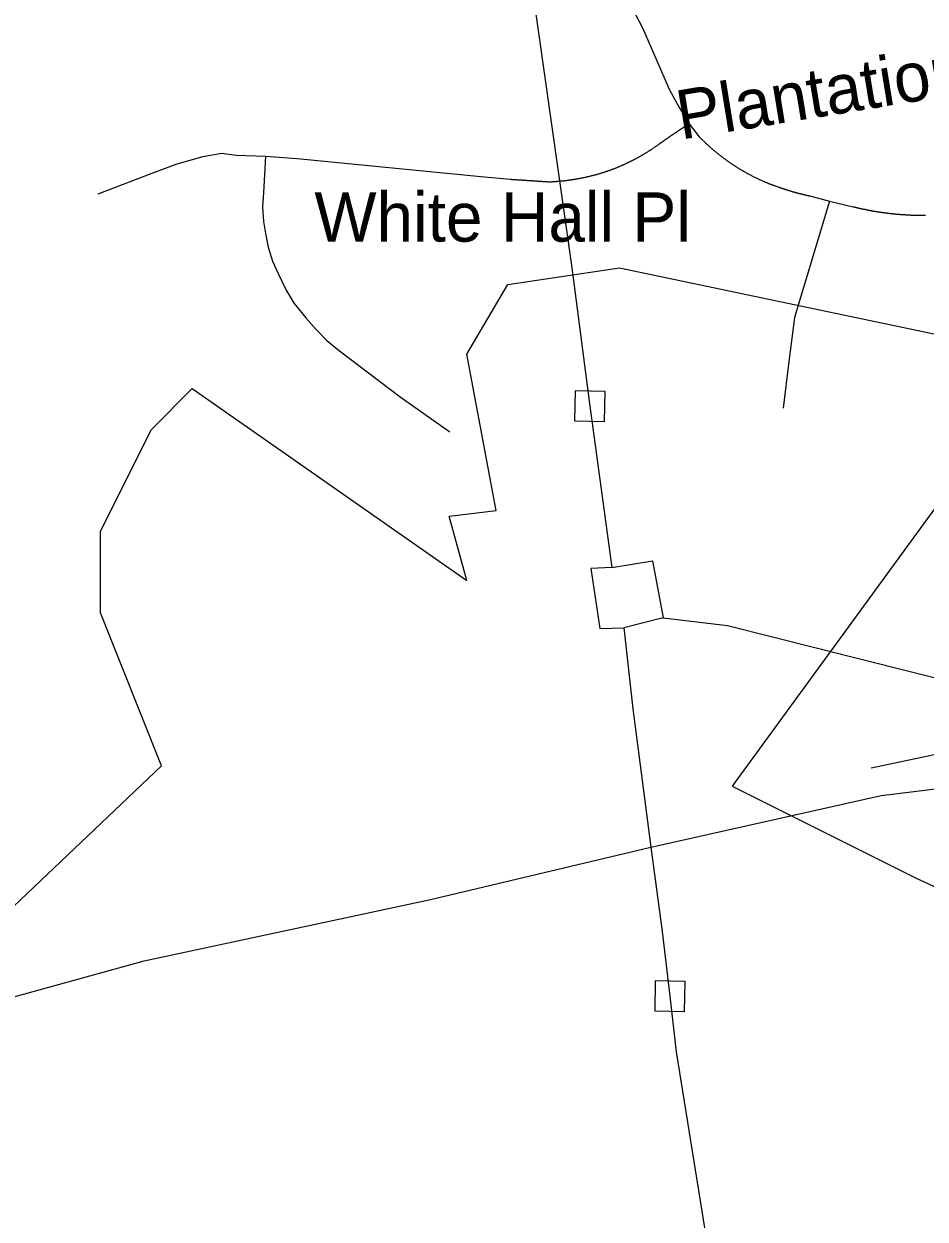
# Model space of a CAD drawing. Extents: x 1268485 to 1426702, y 514839 to 616766.
# Drawn here: x 1349734 to 1350936, y 537670 to 539264 of the extents above; entities that cross this region are included whole.
import ezdxf

# ---------------------------------------------------------------- set-up
doc = ezdxf.new("R2010")
doc.units = 0
for name, color, linetype in [('Old_Level_10', 7, 'Continuous'), ('Old_Level_35', 7, 'Continuous'), ('Old_Level_48', 7, 'Continuous'), ('Old_Level_49', 7, 'Continuous'), ('Old_Level_56', 7, 'Continuous')]:
    doc.layers.add(name, color=color, linetype=linetype)

msp = doc.modelspace()

# ---------------------------------------------------------------- linework, layer by layer
at = {"layer": 'Old_Level_35'}
for p, q in [((1350621.787, 539131.294), (1350635.218, 539113.762)), ((1350782.65, 539034.92), (1350808.897, 539027.794)), ((1350808.897, 539027.794), (1350840.372, 539020.617)), ((1351045.117, 538310.061), (1350864.261, 538271.613))]:
    msp.add_line(p, q, dxfattribs=at)
for points in [[(1350445.134, 539376.332), (1350463.384, 539365.464), (1350472.509, 539359.568), (1350482.249, 539350.751), (1350495.167, 539339.627), (1350509.11, 539327.58), (1350523.464, 539313.175), (1350536.485, 539297.437), (1350549.506, 539277.957), (1350559.656, 539258.939), (1350583.339, 539204.19), (1350594.925, 539177.328), (1350607.843, 539153.645), (1350621.787, 539131.294)], [(1350579.751, 539102.792), (1350580.264, 539103.15), (1350580.674, 539103.458), (1350580.981, 539103.663), (1350581.494, 539104.022), (1350581.904, 539104.33), (1350582.212, 539104.638), (1350582.724, 539104.893), (1350583.134, 539105.201), (1350583.544, 539105.509), (1350583.955, 539105.816), (1350584.365, 539106.073), (1350584.877, 539106.38), (1350585.287, 539106.688), (1350585.595, 539106.996), (1350586.108, 539107.252), (1350586.518, 539107.559), (1350586.825, 539107.867), (1350587.338, 539108.123), (1350587.748, 539108.431), (1350588.158, 539108.739), (1350588.671, 539109.046), (1350588.978, 539109.302), (1350589.388, 539109.61), (1350589.901, 539109.917), (1350590.209, 539110.174), (1350590.619, 539110.481), (1350591.131, 539110.789), (1350591.541, 539111.045), (1350591.849, 539111.353), (1350592.362, 539111.712), (1350592.772, 539111.917), (1350593.284, 539112.275), (1350593.592, 539112.583), (1350594.002, 539112.788), (1350594.515, 539113.147), (1350594.925, 539113.455), (1350595.232, 539113.711), (1350595.745, 539114.018), (1350596.155, 539114.326), (1350596.668, 539114.583), (1350596.975, 539114.89), (1350597.385, 539115.198), (1350597.898, 539115.454), (1350598.206, 539115.761), (1350598.616, 539116.018), (1350599.128, 539116.325), (1350599.538, 539116.633), (1350600.051, 539116.889), (1350600.359, 539117.197), (1350600.769, 539117.453), (1350601.281, 539117.761), (1350601.589, 539118.068), (1350602.102, 539118.324), (1350602.512, 539118.632), (1350602.922, 539118.889), (1350603.332, 539119.196), (1350603.742, 539119.504), (1350604.255, 539119.76), (1350604.665, 539120.067), (1350604.972, 539120.324), (1350605.485, 539120.632), (1350605.895, 539120.887), (1350606.408, 539121.195), (1350606.715, 539121.503), (1350607.125, 539121.759), (1350607.638, 539122.067), (1350608.048, 539122.323), (1350608.458, 539122.63), (1350608.868, 539122.887), (1350609.278, 539123.195), (1350609.791, 539123.451), (1350610.099, 539123.758), (1350610.611, 539124.015), (1350611.021, 539124.323), (1350611.329, 539124.578), (1350611.842, 539124.886), (1350612.252, 539125.143), (1350612.764, 539125.45), (1350613.174, 539125.706), (1350613.585, 539126.014), (1350613.995, 539126.271), (1350614.405, 539126.578), (1350614.917, 539126.834), (1350615.225, 539127.142), (1350615.738, 539127.398), (1350616.148, 539127.706), (1350616.66, 539127.962), (1350616.968, 539128.269), (1350617.378, 539128.526), (1350617.891, 539128.834), (1350618.301, 539129.039), (1350618.711, 539129.397), (1350619.121, 539129.602), (1350619.634, 539129.961), (1350620.044, 539130.166), (1350620.351, 539130.422), (1350620.864, 539130.73), (1350621.274, 539130.987), (1350621.787, 539131.294)], [(1350635.218, 539113.762), (1350636.038, 539112.993), (1350636.755, 539112.275), (1350637.473, 539111.507), (1350638.293, 539110.737), (1350639.011, 539110.02), (1350639.729, 539109.251), (1350640.549, 539108.482), (1350641.267, 539107.764), (1350641.984, 539106.996), (1350642.907, 539106.226), (1350643.625, 539105.509), (1350644.342, 539104.791), (1350645.163, 539104.073), (1350645.983, 539103.356), (1350646.7, 539102.638), (1350647.521, 539101.92), (1350648.238, 539101.202), (1350649.161, 539100.485), (1350649.879, 539099.767), (1350650.801, 539099.049), (1350651.519, 539098.383), (1350652.339, 539097.666), (1350653.16, 539096.999), (1350653.877, 539096.333), (1350654.8, 539095.615), (1350655.62, 539094.948), (1350656.338, 539094.231), (1350657.261, 539093.565), (1350657.978, 539092.898), (1350658.901, 539092.18), (1350659.721, 539091.514), (1350660.541, 539090.899), (1350661.362, 539090.181), (1350662.284, 539089.566), (1350663.002, 539088.899), (1350663.925, 539088.233), (1350664.745, 539087.567), (1350665.668, 539086.951), (1350666.385, 539086.336), (1350667.206, 539085.619), (1350668.128, 539085.003), (1350669.051, 539084.388), (1350669.871, 539083.773), (1350670.794, 539083.107), (1350671.614, 539082.492), (1350672.537, 539081.877), (1350673.357, 539081.262), (1350674.28, 539080.697), (1350675.1, 539080.082), (1350676.023, 539079.416), (1350676.843, 539078.801), (1350677.766, 539078.237), (1350678.586, 539077.621), (1350679.509, 539077.058), (1350680.329, 539076.443), (1350681.252, 539075.879), (1350682.174, 539075.315), (1350682.995, 539074.751), (1350684.02, 539074.136), (1350684.84, 539073.572), (1350685.763, 539073.008), (1350686.583, 539072.444), (1350687.608, 539071.88), (1350688.531, 539071.317), (1350689.351, 539070.752), (1350690.274, 539070.24), (1350691.299, 539069.676), (1350692.119, 539069.112), (1350693.042, 539068.651), (1350693.965, 539068.087), (1350694.888, 539067.574), (1350695.913, 539067.01), (1350696.733, 539066.498), (1350697.758, 539065.934), (1350698.579, 539065.421), (1350699.501, 539064.96), (1350700.527, 539064.447), (1350701.347, 539063.935), (1350702.372, 539063.422), (1350703.397, 539062.96), (1350704.218, 539062.448), (1350705.243, 539061.935), (1350706.166, 539061.422), (1350707.088, 539061.012), (1350708.114, 539060.5), (1350709.036, 539059.987), (1350709.959, 539059.577), (1350710.882, 539059.064), (1350711.907, 539058.603), (1350712.83, 539058.142), (1350713.855, 539057.681), (1350714.778, 539057.27), (1350715.7, 539056.809), (1350716.726, 539056.399), (1350717.751, 539055.886), (1350718.674, 539055.425), (1350719.596, 539055.066), (1350720.622, 539054.605), (1350721.647, 539054.195)], [(1349833.259, 539037.585), (1349907.59, 539066.293), (1349937.425, 539077.366), (1349973.002, 539087.311), (1349998.326, 539091.77), (1350017.293, 539089.259), (1350056.458, 539088.131)], [(1350056.458, 539088.131), (1350055.228, 539062.858), (1350053.792, 539039.482), (1350052.665, 539020.617), (1350053.792, 539000.624), (1350056.458, 538984.835), (1350060.251, 538966.688), (1350065.89, 538947.824), (1350073.375, 538931.624), (1350084.038, 538909.376), (1350094.905, 538891.332), (1350110.387, 538872.416), (1350123.51, 538857.396), (1350138.581, 538842.273), (1350155.293, 538828.33), (1350236.289, 538766.865), (1350302.623, 538720.523)], [(1350056.458, 539088.131), (1350099.006, 539084.747), (1350343.736, 539060.961), (1350383.414, 539057.168)], [(1350514.954, 539068.856), (1350515.672, 539069.112), (1350516.39, 539069.369), (1350517.005, 539069.624), (1350517.723, 539069.881), (1350518.338, 539070.189), (1350519.158, 539070.445), (1350519.876, 539070.701), (1350520.491, 539070.957), (1350521.209, 539071.265), (1350521.926, 539071.522), (1350522.644, 539071.727), (1350523.259, 539072.085), (1350523.977, 539072.29), (1350524.592, 539072.547), (1350525.412, 539072.854), (1350526.027, 539073.11), (1350526.745, 539073.418), (1350527.36, 539073.725), (1350528.078, 539073.982), (1350528.795, 539074.29), (1350529.513, 539074.546), (1350530.128, 539074.853), (1350530.743, 539075.213), (1350531.461, 539075.52), (1350532.076, 539075.776), (1350532.897, 539076.084), (1350533.512, 539076.391), (1350534.229, 539076.699), (1350534.845, 539077.006), (1350535.46, 539077.314), (1350536.28, 539077.621), (1350536.895, 539077.929), (1350537.613, 539078.237), (1350538.228, 539078.544), (1350538.843, 539078.852), (1350539.663, 539079.211), (1350540.278, 539079.519), (1350540.894, 539079.826), (1350541.611, 539080.134), (1350542.226, 539080.441), (1350542.842, 539080.8), (1350543.662, 539081.107), (1350544.277, 539081.415), (1350544.892, 539081.825), (1350545.61, 539082.133), (1350546.225, 539082.44), (1350546.84, 539082.799), (1350547.455, 539083.107), (1350548.275, 539083.517), (1350548.891, 539083.825), (1350549.506, 539084.183), (1350550.121, 539084.491), (1350550.839, 539084.901), (1350551.454, 539085.208), (1350552.171, 539085.568), (1350552.787, 539085.926), (1350553.504, 539086.234), (1350554.119, 539086.644), (1350554.735, 539087.003), (1350555.35, 539087.361), (1350555.965, 539087.669), (1350556.58, 539088.079), (1350557.4, 539088.438), (1350558.015, 539088.797), (1350558.631, 539089.207), (1350559.246, 539089.566), (1350559.861, 539089.925), (1350560.476, 539090.335), (1350561.091, 539090.694), (1350561.706, 539091.052), (1350562.527, 539091.463), (1350563.142, 539091.822), (1350563.757, 539092.18), (1350564.372, 539092.642), (1350564.987, 539093), (1350565.602, 539093.36), (1350566.218, 539093.77), (1350566.833, 539094.18), (1350567.55, 539094.538), (1350568.165, 539094.948), (1350568.781, 539095.358), (1350569.396, 539095.769), (1350570.011, 539096.179), (1350570.626, 539096.538), (1350571.241, 539096.948), (1350571.856, 539097.358), (1350572.472, 539097.819), (1350573.087, 539098.178), (1350573.702, 539098.639), (1350574.42, 539098.999), (1350575.035, 539099.46), (1350575.547, 539099.87), (1350576.163, 539100.229), (1350576.778, 539100.69), (1350577.393, 539101.1), (1350578.008, 539101.562), (1350578.623, 539101.92), (1350579.238, 539102.382), (1350579.751, 539102.792)], [(1350383.414, 539057.168), (1350383.926, 539057.168), (1350384.336, 539057.116), (1350384.849, 539057.065), (1350385.362, 539057.065), (1350385.977, 539057.014), (1350386.489, 539057.014), (1350387.002, 539056.963), (1350387.515, 539056.963), (1350388.027, 539056.86), (1350388.54, 539056.86), (1350388.95, 539056.809), (1350389.668, 539056.809), (1350390.078, 539056.758), (1350390.59, 539056.706), (1350391.103, 539056.706), (1350391.616, 539056.604), (1350392.128, 539056.604), (1350392.641, 539056.553), (1350393.256, 539056.553), (1350393.769, 539056.501), (1350394.281, 539056.501), (1350394.794, 539056.45), (1350395.204, 539056.45), (1350395.717, 539056.399), (1350396.229, 539056.399), (1350396.844, 539056.296), (1350397.357, 539056.245), (1350397.87, 539056.245), (1350398.382, 539056.194), (1350398.895, 539056.194), (1350399.408, 539056.143), (1350399.92, 539056.143), (1350400.535, 539056.04), (1350401.048, 539056.04), (1350401.458, 539055.988), (1350401.971, 539055.988), (1350402.483, 539055.938), (1350402.996, 539055.886), (1350403.509, 539055.886), (1350404.124, 539055.835), (1350404.636, 539055.835), (1350405.149, 539055.733), (1350405.662, 539055.733), (1350406.174, 539055.681), (1350406.584, 539055.681), (1350407.097, 539055.63), (1350407.712, 539055.578), (1350408.225, 539055.578), (1350408.738, 539055.476), (1350409.25, 539055.476), (1350409.763, 539055.425), (1350410.275, 539055.425), (1350410.891, 539055.373), (1350411.403, 539055.373), (1350411.916, 539055.322), (1350412.326, 539055.322), (1350412.839, 539055.271), (1350413.351, 539055.168), (1350413.864, 539055.168), (1350414.479, 539055.117), (1350414.992, 539055.117), (1350415.504, 539055.066), (1350416.017, 539055.066), (1350416.529, 539055.015), (1350417.042, 539055.015), (1350417.452, 539054.963), (1350418.17, 539054.861), (1350418.58, 539054.861), (1350419.093, 539054.81), (1350419.605, 539054.81), (1350420.118, 539054.758), (1350420.631, 539054.758), (1350421.143, 539054.707), (1350421.758, 539054.707), (1350422.271, 539054.605), (1350422.784, 539054.605), (1350423.296, 539054.553), (1350423.706, 539054.502), (1350424.219, 539054.502), (1350424.732, 539054.451), (1350425.347, 539054.451), (1350425.859, 539054.4), (1350426.372, 539054.4), (1350426.885, 539054.297), (1350427.397, 539054.297), (1350427.91, 539054.246), (1350428.423, 539054.195), (1350429.038, 539054.195), (1350429.55, 539054.143), (1350429.96, 539054.143), (1350430.473, 539054.04), (1350430.986, 539054.04), (1350431.498, 539053.99), (1350432.011, 539053.99), (1350432.626, 539053.938), (1350433.139, 539053.887), (1350433.651, 539053.887), (1350434.164, 539053.835), (1350434.677, 539053.835)], [(1350434.677, 539053.835), (1350435.497, 539053.835), (1350436.214, 539053.887), (1350437.137, 539053.887), (1350437.957, 539053.938), (1350438.778, 539053.99), (1350439.598, 539054.04), (1350440.418, 539054.04), (1350441.238, 539054.143), (1350442.161, 539054.195), (1350442.879, 539054.246), (1350443.801, 539054.297), (1350444.622, 539054.4), (1350445.339, 539054.451), (1350446.262, 539054.502), (1350446.98, 539054.553), (1350447.902, 539054.605), (1350448.723, 539054.707), (1350449.543, 539054.758), (1350450.363, 539054.861), (1350451.081, 539054.963), (1350452.003, 539055.015), (1350452.926, 539055.066), (1350453.644, 539055.168), (1350454.464, 539055.271), (1350455.284, 539055.373), (1350456.105, 539055.425), (1350456.925, 539055.578), (1350457.745, 539055.63), (1350458.668, 539055.733), (1350459.385, 539055.886), (1350460.206, 539055.938), (1350461.026, 539056.04), (1350461.846, 539056.194), (1350462.666, 539056.296), (1350463.486, 539056.45), (1350464.409, 539056.553), (1350465.127, 539056.706), (1350466.05, 539056.758), (1350466.767, 539056.963), (1350467.587, 539057.065), (1350468.408, 539057.168), (1350469.228, 539057.321), (1350470.048, 539057.424), (1350470.868, 539057.578), (1350471.586, 539057.681), (1350472.509, 539057.886), (1350473.329, 539057.988), (1350474.149, 539058.142), (1350474.969, 539058.296), (1350475.79, 539058.449), (1350476.61, 539058.603), (1350477.327, 539058.757), (1350478.25, 539058.962), (1350478.968, 539059.064), (1350479.891, 539059.269), (1350480.608, 539059.424), (1350481.531, 539059.577), (1350482.249, 539059.731), (1350483.171, 539059.936), (1350483.889, 539060.141), (1350484.607, 539060.295), (1350485.53, 539060.5), (1350486.247, 539060.705), (1350487.17, 539060.859), (1350487.888, 539061.064), (1350488.708, 539061.269), (1350489.528, 539061.422), (1350490.348, 539061.627), (1350491.168, 539061.832), (1350491.989, 539061.987), (1350492.706, 539062.243), (1350493.527, 539062.448), (1350494.347, 539062.602), (1350495.167, 539062.858), (1350495.987, 539063.063), (1350496.705, 539063.268), (1350497.525, 539063.525), (1350498.345, 539063.678), (1350499.165, 539063.935), (1350499.986, 539064.191), (1350500.703, 539064.396), (1350501.524, 539064.601), (1350502.344, 539064.857), (1350503.164, 539065.062), (1350503.882, 539065.318), (1350504.702, 539065.575), (1350505.522, 539065.831), (1350506.24, 539066.088), (1350507.163, 539066.293), (1350507.88, 539066.549), (1350508.598, 539066.805), (1350509.521, 539067.061), (1350510.238, 539067.318), (1350510.956, 539067.574), (1350511.879, 539067.831), (1350512.596, 539068.087), (1350513.417, 539068.394), (1350514.134, 539068.651), (1350514.954, 539068.856)], [(1350721.647, 539054.195), (1350722.16, 539053.938), (1350722.775, 539053.682), (1350723.39, 539053.425), (1350724.005, 539053.169), (1350724.62, 539052.913), (1350725.133, 539052.708), (1350725.748, 539052.452), (1350726.363, 539052.195), (1350726.978, 539051.939), (1350727.593, 539051.734), (1350728.106, 539051.477), (1350728.721, 539051.272), (1350729.336, 539051.016), (1350729.952, 539050.76), (1350730.669, 539050.555), (1350731.284, 539050.299), (1350731.797, 539050.042), (1350732.412, 539049.837), (1350733.027, 539049.632), (1350733.643, 539049.376), (1350734.258, 539049.119), (1350734.873, 539048.914), (1350735.488, 539048.709), (1350736.001, 539048.504), (1350736.616, 539048.248), (1350737.231, 539048.043), (1350737.846, 539047.838), (1350738.461, 539047.581), (1350739.076, 539047.376), (1350739.794, 539047.171), (1350740.409, 539046.915), (1350740.922, 539046.761), (1350741.537, 539046.505), (1350742.152, 539046.3), (1350742.767, 539046.043), (1350743.383, 539045.89), (1350743.998, 539045.685), (1350744.613, 539045.428), (1350745.228, 539045.275), (1350745.843, 539045.07), (1350746.458, 539044.813), (1350746.971, 539044.608), (1350747.586, 539044.455), (1350748.201, 539044.25), (1350748.919, 539043.993), (1350749.534, 539043.788), (1350750.149, 539043.635), (1350750.764, 539043.429), (1350751.38, 539043.275), (1350751.995, 539043.07), (1350752.61, 539042.865), (1350753.225, 539042.712), (1350753.84, 539042.507), (1350754.455, 539042.25), (1350755.173, 539042.045), (1350755.788, 539041.892), (1350756.403, 539041.687), (1350757.018, 539041.584), (1350757.634, 539041.379), (1350758.249, 539041.174), (1350758.864, 539041.02), (1350759.479, 539040.815), (1350759.992, 539040.61), (1350760.607, 539040.456), (1350761.222, 539040.251), (1350761.837, 539040.046), (1350762.452, 539039.944), (1350763.17, 539039.739), (1350763.785, 539039.584), (1350764.4, 539039.379), (1350765.015, 539039.226), (1350765.631, 539039.072), (1350766.246, 539038.867), (1350766.861, 539038.764), (1350767.476, 539038.559), (1350768.091, 539038.354), (1350768.706, 539038.251), (1350769.424, 539038.046), (1350770.142, 539037.944), (1350770.757, 539037.739), (1350771.372, 539037.636), (1350771.987, 539037.431), (1350772.602, 539037.226), (1350773.218, 539037.124), (1350773.833, 539037.021), (1350774.55, 539036.816), (1350775.166, 539036.714), (1350775.781, 539036.509), (1350776.396, 539036.355), (1350777.011, 539036.253), (1350777.626, 539036.048), (1350778.241, 539035.945), (1350778.857, 539035.791), (1350779.472, 539035.637), (1350780.087, 539035.483), (1350780.702, 539035.381), (1350781.42, 539035.227), (1350782.035, 539035.073), (1350782.65, 539034.92)], [(1350808.897, 539027.794), (1350762.35, 538872.621), (1350754.66, 538814.232), (1350746.868, 538751.999)], [(1350840.372, 539020.617), (1350840.987, 539020.464), (1350841.705, 539020.259), (1350842.423, 539020.104), (1350843.038, 539019.951), (1350843.755, 539019.797), (1350844.371, 539019.643), (1350844.986, 539019.438), (1350845.703, 539019.336), (1350846.421, 539019.131), (1350847.139, 539018.977), (1350847.754, 539018.823), (1350848.369, 539018.669), (1350849.087, 539018.516), (1350849.702, 539018.361), (1350850.522, 539018.208), (1350851.137, 539018.054), (1350851.753, 539017.9), (1350852.47, 539017.746), (1350853.085, 539017.644), (1350853.906, 539017.439), (1350854.521, 539017.336), (1350855.136, 539017.183), (1350855.854, 539017.08), (1350856.469, 539016.875), (1350857.289, 539016.773), (1350857.904, 539016.618), (1350858.519, 539016.516), (1350859.237, 539016.363), (1350859.852, 539016.208), (1350860.672, 539016.055), (1350861.287, 539015.952), (1350862.005, 539015.798), (1350862.62, 539015.696), (1350863.235, 539015.542), (1350863.953, 539015.44), (1350864.671, 539015.337), (1350865.388, 539015.183), (1350866.004, 539015.081), (1350866.721, 539014.927), (1350867.336, 539014.825), (1350868.157, 539014.67), (1350868.772, 539014.568), (1350869.387, 539014.517), (1350870.105, 539014.363), (1350870.72, 539014.26), (1350871.54, 539014.107), (1350872.155, 539014.004), (1350872.873, 539013.953), (1350873.488, 539013.799), (1350874.206, 539013.697), (1350874.923, 539013.543), (1350875.641, 539013.492), (1350876.256, 539013.389), (1350876.974, 539013.338), (1350877.589, 539013.184), (1350878.204, 539013.082), (1350879.024, 539012.979), (1350879.64, 539012.877), (1350880.357, 539012.825), (1350880.972, 539012.672), (1350881.793, 539012.62), (1350882.408, 539012.517), (1350883.125, 539012.415), (1350883.741, 539012.312), (1350884.458, 539012.262), (1350885.176, 539012.21), (1350885.894, 539012.056), (1350886.509, 539012.005), (1350887.227, 539011.954), (1350887.842, 539011.8), (1350888.662, 539011.749), (1350889.277, 539011.697), (1350889.995, 539011.646), (1350890.61, 539011.492), (1350891.328, 539011.441), (1350892.045, 539011.39), (1350892.763, 539011.339), (1350893.378, 539011.236), (1350894.096, 539011.185), (1350894.711, 539011.134), (1350895.531, 539011.082), (1350896.146, 539010.929), (1350896.864, 539010.877), (1350897.479, 539010.826), (1350898.299, 539010.775), (1350898.915, 539010.775), (1350899.632, 539010.672), (1350900.247, 539010.621), (1350900.965, 539010.569), (1350901.58, 539010.519), (1350902.4, 539010.416), (1350903.016, 539010.364), (1350903.733, 539010.314), (1350904.348, 539010.314), (1350905.169, 539010.262), (1350905.784, 539010.211), (1350906.501, 539010.109), (1350907.117, 539010.109), (1350907.834, 539010.057)], [(1350907.834, 539010.057), (1350908.449, 539010.006), (1350909.167, 539009.954), (1350909.782, 539009.954), (1350910.397, 539009.852), (1350911.013, 539009.801), (1350911.628, 539009.801), (1350912.243, 539009.749), (1350912.858, 539009.749), (1350913.473, 539009.698), (1350914.088, 539009.698), (1350914.704, 539009.647), (1350915.421, 539009.647), (1350916.036, 539009.544), (1350916.652, 539009.544), (1350917.267, 539009.493), (1350917.882, 539009.493), (1350918.6, 539009.493), (1350919.215, 539009.442), (1350919.83, 539009.442), (1350920.548, 539009.442), (1350921.163, 539009.391), (1350921.778, 539009.391), (1350922.393, 539009.391), (1350923.008, 539009.391), (1350923.623, 539009.391), (1350924.238, 539009.288), (1350924.854, 539009.288), (1350925.469, 539009.288), (1350926.084, 539009.288), (1350926.802, 539009.288), (1350927.417, 539009.288), (1350928.032, 539009.288), (1350928.647, 539009.288), (1350929.262, 539009.288), (1350929.877, 539009.288), (1350930.493, 539009.288), (1350931.108, 539009.288), (1350931.723, 539009.288), (1350932.338, 539009.391), (1350932.953, 539009.391), (1350933.773, 539009.391), (1350934.389, 539009.391), (1350935.004, 539009.442), (1350935.619, 539009.442), (1350936.234, 539009.442), (1350936.849, 539009.442)]]:
    msp.add_lwpolyline(points, dxfattribs=at)
at = {"layer": 'Old_Level_48'}
msp.add_lwpolyline([(1349388.124, 537772.025), (1349918.064, 538275.035), (1349836.535, 538478.957), (1349836.535, 538587.716), (1349904.476, 538723.664), (1349958.829, 538778.044), (1350325.034, 538522.309), (1350301.541, 538607.915), (1350364.188, 538615.359), (1350325.034, 538823.791), (1350379.849, 538916.84), (1350528.634, 538939.172), (1351096.366, 538820.068), (1350679.004, 538247.845), (1350923.591, 538125.491), (1351100.238, 538043.922), (1351548.648, 538356.603), (1351997.059, 538750.854), (1352336.764, 539049.94)], dxfattribs=at)
at = {"layer": 'Old_Level_49'}
msp.add_lwpolyline([(1349388.124, 537772.025), (1349918.064, 538275.035), (1349836.535, 538478.957), (1349836.535, 538587.716), (1349904.476, 538723.664), (1349958.829, 538778.044), (1350325.034, 538522.309), (1350301.541, 538607.915), (1350364.188, 538615.359), (1350325.034, 538823.791), (1350379.849, 538916.84), (1350528.634, 538939.172), (1351096.366, 538820.068), (1350679.004, 538247.845), (1350923.591, 538125.491), (1351100.238, 538043.922), (1351548.648, 538356.603), (1351997.059, 538750.854), (1352336.764, 539049.94)], dxfattribs=at)
at = {"layer": 'Old_Level_56'}
for points in [[(1350299.871, 540149.315), (1350331.995, 539876.538), (1350394.43, 539437.705), (1350465.382, 538939.005), (1350489.277, 538754.436), (1350518.564, 538539.544)], [(1350587.039, 538472.135), (1350672.647, 538462.059), (1351400.261, 538279.131), (1351411.912, 538278.808), (1351432.37, 538293.031), (1351630.442, 538459.022), (1351970.05, 538763.318), (1352253.548, 539026.254), (1352430.734, 539108.976), (1352534.093, 539123.748), (1352562.815, 539111.276), (1352593.155, 539088.296), (1352912.09, 538807.634), (1353015.45, 538701.278), (1353146.355, 538557.875)], [(1350468.873, 538734.838), (1350508.876, 538734.032), (1350509.681, 538774.035), (1350469.678, 538774.841), (1350468.873, 538734.838)], [(1350570.474, 538166.322), (1350578.516, 538168.161), (1350878.012, 538235.566), (1351088.62, 538260.941), (1351584.562, 538335.996), (1352044.425, 538407.977), (1352454.043, 538468.964), (1353146.355, 538557.875), (1353925.027, 538662.656)], [(1350518.564, 538539.544), (1350572.769, 538548.458), (1350587.039, 538472.135), (1350534.754, 538459.18)], [(1350518.564, 538539.544), (1350490.526, 538538.308), (1350502.716, 538458.025), (1350534.754, 538459.18)], [(1350534.754, 538459.18), (1350546.379, 538350.895), (1350551.692, 538310.201), (1350570.474, 538166.322)], [(1344423.965, 536474.59), (1344805.477, 536620.384), (1345406.359, 536829.193), (1345823.065, 536944.064), (1346326.178, 537077.205), (1346829.367, 537204.14), (1347320.355, 537331.322), (1347761.062, 537445.709), (1348187.89, 537566.378), (1348602.475, 537675.288), (1349101.829, 537810.504), (1349492.091, 537903.896), (1349894.715, 538015.047), (1350276.739, 538096.799), (1350570.474, 538166.322)], [(1350570.474, 538166.322), (1350585.82, 538053.96), (1350596.088, 537967.711), (1350604.398, 537893.509), (1350695.995, 537324.994), (1350814.123, 536514.03), (1350844.171, 536316.097), (1350859.523, 536214.974), (1350865.672, 536132.81), (1350877.338, 536026.525), (1350912.893, 535725.466)], [(1350575.684, 537948.113), (1350615.687, 537947.307), (1350616.492, 537987.31), (1350576.49, 537988.116), (1350575.684, 537948.113)]]:
    msp.add_lwpolyline(points, dxfattribs=at)

# ---------------------------------------------------------------- texts
at = {"layer": 'Old_Level_10'}
msp.add_text('Plantation Trl', height=65.61666, rotation=9.292967, dxfattribs=at).set_placement((1350610.554, 539109.851))
msp.add_text('White Hall Pl', height=65.61666, dxfattribs=at).set_placement((1350121.825, 538973.976))

doc.saveas('drawing.dxf')
